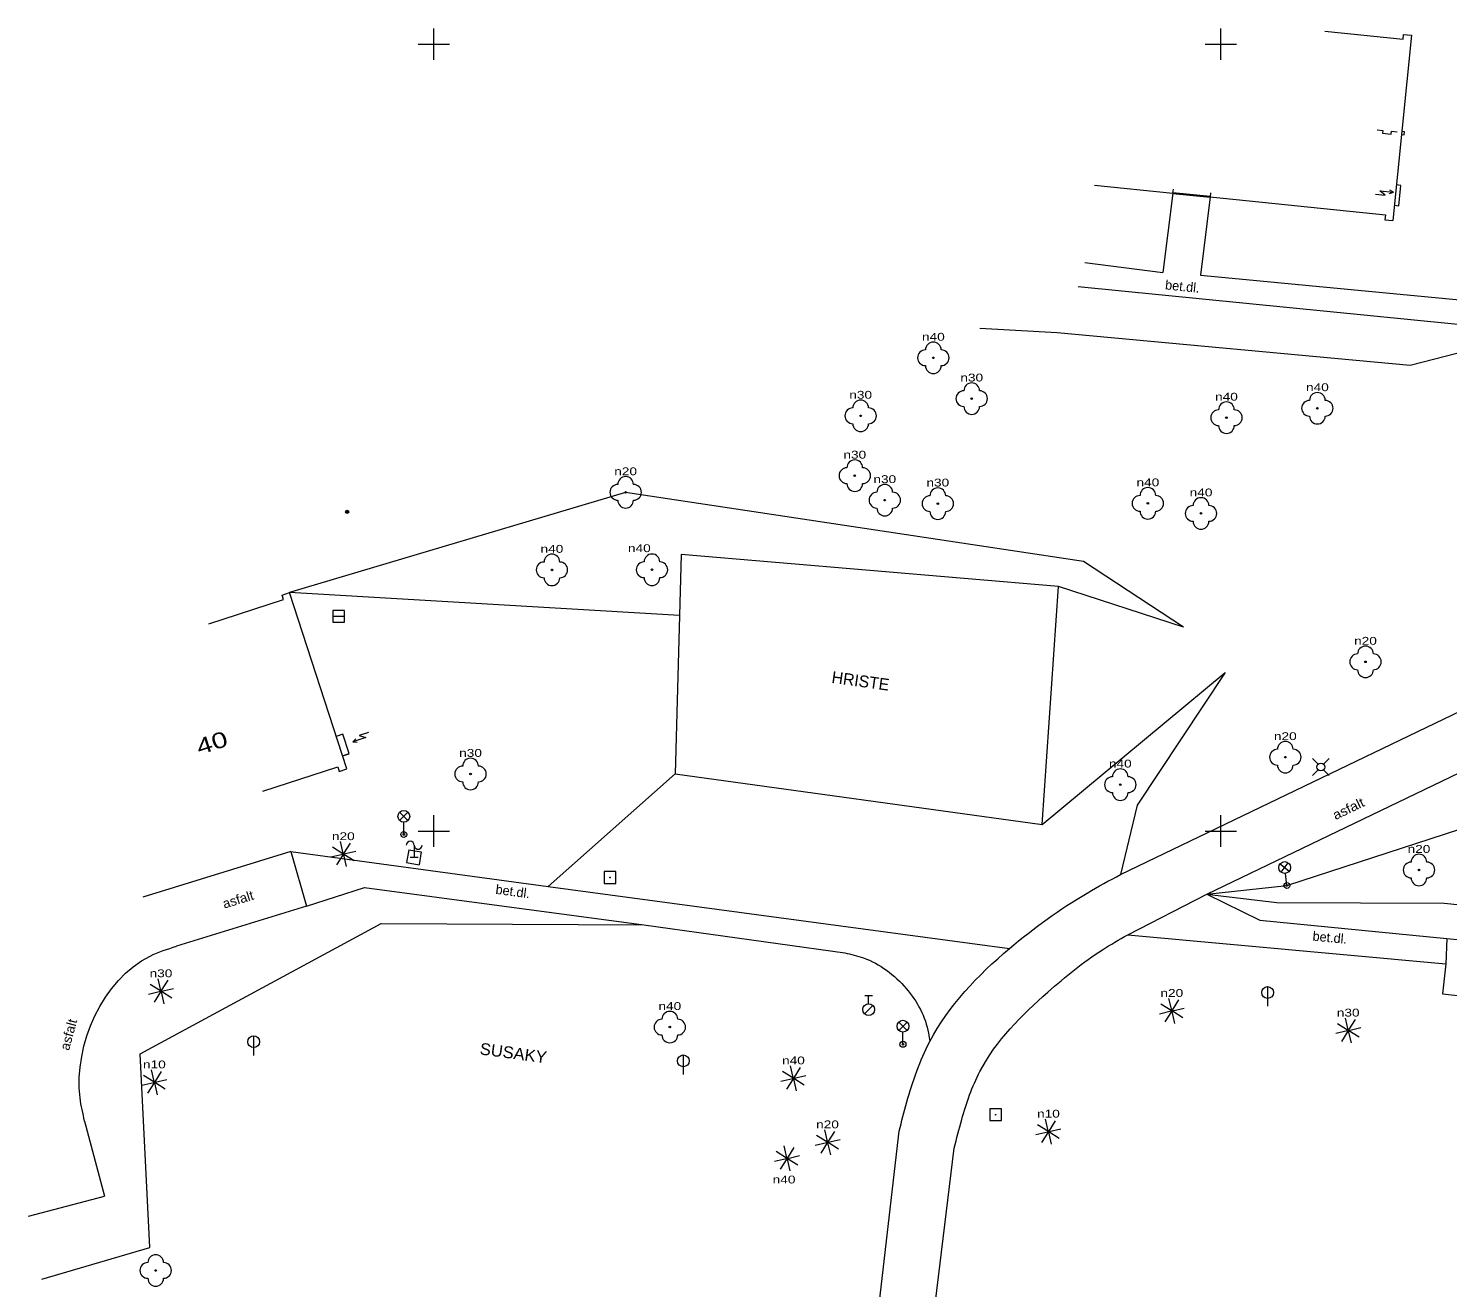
# Model space of a CAD drawing. Extents: x -670514 to -669423, y -1130798 to -1130123.
# Drawn here: x -670375.8 to -670285.6, y -1130379 to -1130299 of the extents above; entities that cross this region are included whole.
import ezdxf
from ezdxf.enums import TextEntityAlignment as Align

# ---------------------------------------------------------------- set-up
doc = ezdxf.new("R2010")
doc.units = 0
doc.header["$LTSCALE"] = 0.24
for name, color, linetype, lineweight in [('10', 7, 'Continuous', 13), ('11', 7, 'Continuous', 13), ('14', 7, 'Continuous', 13), ('22', 7, 'Continuous', 13), ('24', 7, 'Continuous', 13), ('25', 7, 'Continuous', 13), ('26', 7, 'Continuous', 13), ('27', 7, 'Continuous', 13), ('28', 7, 'Continuous', 13), ('31', 7, 'Continuous', 13), ('33', 7, 'Continuous', 13), ('36', 7, 'Continuous', 13), ('5', 7, 'Continuous', 13), ('6', 7, 'Continuous', 13), ('61', 7, 'Continuous', 13)]:
    doc.layers.add(name, color=color, linetype=linetype, lineweight=lineweight)
for name, color, linetype in [('40', 7, 'Continuous'), ('42', 7, 'Continuous'), ('44', 7, 'Continuous'), ('47', 7, 'Continuous')]:
    doc.layers.add(name, color=color, linetype=linetype)

msp = doc.modelspace()

# ---------------------------------------------------------------- linework, layer by layer
at = {"layer": '10'}
for p, q in [((-670303.039, -1130309.464), (-670303.685, -1130314.506)), ((-670308.644, -1130313.871), (-670303.685, -1130314.506)), ((-670306.368, -1130352.764), (-670262.03, -1130331.413)), ((-670359.087, -1130351.292), (-670368.502, -1130354.2)), ((-670358.089, -1130354.765), (-670366.357, -1130357.318)), ((-670305.915, -1130356.591), (-670285.692, -1130358.448)), ((-670285.636, -1130356.823), (-670266.032, -1130358.753)), ((-670285.692, -1130358.448), (-670285.913, -1130360.345)), ((-670372.192, -1130368.439), (-670370.934, -1130373.204)), ((-670323.828, -1130398.418), (-670320.435, -1130369.067)), ((-670375.768, -1130374.48), (-670370.934, -1130373.204))]:
    msp.add_line(p, q, dxfattribs=at)
for points in [[(-670300.676, -1130309.705), (-670301.286, -1130314.671), (-670268.591, -1130317.8)], [(-670262.03, -1130331.413), (-670267.808, -1130319.479), (-670279.819, -1130318.323), (-670309.071, -1130315.428)], [(-670305.915, -1130356.591), (-670300.884, -1130354.022), (-670260.5, -1130334.581)], [(-670359.087, -1130351.292), (-670342.735, -1130353.527), (-670313.434, -1130357.47)], [(-670358.089, -1130354.765), (-670354.419, -1130353.586), (-670336.653, -1130355.956), (-670323.879, -1130357.742)], [(-670300.884, -1130354.022), (-670297.511, -1130355.666), (-670285.636, -1130356.823)], [(-670285.913, -1130360.345), (-670284.549, -1130360.498), (-670266.966, -1130362.23)], [(-670327.052, -1130459.676), (-670322.78, -1130420.826), (-670319.03, -1130387.366), (-670316.938, -1130370.142)]]:
    msp.add_lwpolyline(points, dxfattribs=at)
for points in [[(-670320.435, -1130369.067), (-670319.945, -1130367.218), (-670318.491, -1130363.383), (-670313.434, -1130357.47), (-670308.484, -1130353.939), (-670306.368, -1130352.764)], [(-670316.938, -1130370.142), (-670316.46, -1130368.337), (-670315.299, -1130365.275), (-670310.985, -1130360.231), (-670307.518, -1130357.547), (-670305.915, -1130356.591)], [(-670372.192, -1130368.439), (-670372.481, -1130366.956), (-670368.032, -1130357.945), (-670366.357, -1130357.318)], [(-670323.879, -1130357.742), (-670322.707, -1130358.061), (-670319.988, -1130360.006), (-670318.568, -1130362.849), (-670318.491, -1130363.383)]]:
    msp.add_spline(points, degree=3, dxfattribs=at)
at = {"layer": '11'}
for p, q in [((-670359.087, -1130351.292), (-670358.089, -1130354.765)), ((-670285.636, -1130356.823), (-670285.692, -1130358.448))]:
    msp.add_line(p, q, dxfattribs=at)
msp.add_lwpolyline([(-670334.278, -1130332.433), (-670334.675, -1130346.357), (-670311.35, -1130349.586), (-670310.302, -1130334.46)], close=True, dxfattribs=at)
at = {"layer": '14'}
for p, q in [((-670302.357, -1130337.047), (-670310.302, -1130334.46)), ((-670334.389, -1130336.315), (-670359.169, -1130334.851)), ((-670311.35, -1130349.586), (-670299.73, -1130339.918)), ((-670334.675, -1130346.357), (-670342.735, -1130353.527))]:
    msp.add_line(p, q, dxfattribs=at)
for points in [[(-670279.819, -1130318.323), (-670287.973, -1130320.416), (-670310.397, -1130318.348), (-670315.318, -1130318.069)], [(-670302.357, -1130337.047), (-670308.712, -1130332.866), (-670337.818, -1130328.481), (-670359.169, -1130334.851)], [(-670299.73, -1130339.918), (-670305.304, -1130348.36), (-670306.368, -1130352.764)], [(-670300.884, -1130354.022), (-670295.798, -1130353.463), (-670282.08, -1130348.996)], [(-670300.884, -1130354.022), (-670296.445, -1130354.537), (-670285.8, -1130354.579)], [(-670285.8, -1130354.579), (-670266.083, -1130356.606), (-670253.016, -1130357.115), (-670247.888, -1130360.543)], [(-670374.922, -1130378.465), (-670368.058, -1130376.453), (-670368.663, -1130364.156), (-670353.348, -1130355.882), (-670336.653, -1130355.956)]]:
    msp.add_lwpolyline(points, dxfattribs=at)
at = {"layer": '22'}
for p, q in [((-670355.764, -1130351.425), (-670355.936, -1130350.671)), ((-670355.322, -1130350.775), (-670355.736, -1130351.431)), ((-670356.55, -1130351.645), (-670355.796, -1130351.473)), ((-670355.79, -1130351.445), (-670356.446, -1130351.031)), ((-670355.776, -1130351.499), (-670356.19, -1130352.155)), ((-670355.748, -1130351.505), (-670355.576, -1130352.259)), ((-670355.066, -1130351.899), (-670355.722, -1130351.485)), ((-670355.716, -1130351.457), (-670354.962, -1130351.285)), ((-670367.377, -1130360.157), (-670368.033, -1130359.743)), ((-670367.351, -1130360.137), (-670367.523, -1130359.383)), ((-670366.909, -1130359.487), (-670367.323, -1130360.143)), ((-670368.137, -1130360.357), (-670367.383, -1130360.185)), ((-670367.363, -1130360.211), (-670367.777, -1130360.867)), ((-670367.335, -1130360.217), (-670367.163, -1130360.971)), ((-670366.653, -1130360.611), (-670367.309, -1130360.197)), ((-670367.303, -1130360.169), (-670366.549, -1130359.997)), ((-670303.117, -1130361.387), (-670303.289, -1130360.633)), ((-670302.675, -1130360.737), (-670303.089, -1130361.393)), ((-670303.903, -1130361.607), (-670303.149, -1130361.435)), ((-670303.143, -1130361.407), (-670303.799, -1130360.993)), ((-670303.129, -1130361.461), (-670303.543, -1130362.117)), ((-670303.101, -1130361.467), (-670302.929, -1130362.221)), ((-670302.419, -1130361.861), (-670303.075, -1130361.447)), ((-670303.069, -1130361.419), (-670302.315, -1130361.247)), ((-670292.696, -1130362.855), (-670291.942, -1130362.683)), ((-670291.936, -1130362.655), (-670292.592, -1130362.241)), ((-670291.91, -1130362.635), (-670292.082, -1130361.881)), ((-670291.468, -1130361.985), (-670291.882, -1130362.641)), ((-670291.862, -1130362.667), (-670291.108, -1130362.495)), ((-670291.922, -1130362.709), (-670292.336, -1130363.365)), ((-670291.894, -1130362.715), (-670291.722, -1130363.469)), ((-670291.212, -1130363.109), (-670291.868, -1130362.695)), ((-670367.77, -1130365.925), (-670367.942, -1130365.171)), ((-670367.328, -1130365.275), (-670367.742, -1130365.931)), ((-670327.187, -1130365.692), (-670327.843, -1130365.278)), ((-670327.161, -1130365.672), (-670327.333, -1130364.918)), ((-670326.719, -1130365.022), (-670327.133, -1130365.678)), ((-670368.556, -1130366.145), (-670367.802, -1130365.973)), ((-670367.796, -1130365.945), (-670368.452, -1130365.531)), ((-670367.782, -1130365.999), (-670368.196, -1130366.655)), ((-670367.754, -1130366.005), (-670367.582, -1130366.759)), ((-670367.072, -1130366.399), (-670367.728, -1130365.985)), ((-670367.722, -1130365.957), (-670366.968, -1130365.785)), ((-670327.947, -1130365.892), (-670327.193, -1130365.72)), ((-670327.173, -1130365.746), (-670327.587, -1130366.402)), ((-670327.145, -1130365.752), (-670326.973, -1130366.506)), ((-670326.463, -1130366.146), (-670327.119, -1130365.732)), ((-670327.113, -1130365.704), (-670326.359, -1130365.532)), ((-670324.996, -1130369.735), (-670325.168, -1130368.981)), ((-670310.984, -1130369.076), (-670311.64, -1130368.662)), ((-670310.958, -1130369.056), (-670311.13, -1130368.302)), ((-670310.516, -1130368.406), (-670310.93, -1130369.062)), ((-670310.91, -1130369.088), (-670310.156, -1130368.916)), ((-670325.782, -1130369.955), (-670325.028, -1130369.783)), ((-670325.022, -1130369.755), (-670325.678, -1130369.341)), ((-670325.008, -1130369.809), (-670325.422, -1130370.465)), ((-670324.98, -1130369.815), (-670324.808, -1130370.569)), ((-670324.554, -1130369.085), (-670324.968, -1130369.741)), ((-670324.298, -1130370.209), (-670324.954, -1130369.795)), ((-670324.948, -1130369.767), (-670324.194, -1130369.595)), ((-670311.744, -1130369.276), (-670310.99, -1130369.104)), ((-670310.97, -1130369.13), (-670311.384, -1130369.786)), ((-670310.942, -1130369.136), (-670310.77, -1130369.89)), ((-670310.26, -1130369.53), (-670310.916, -1130369.116)), ((-670327.592, -1130370.786), (-670328.248, -1130370.372)), ((-670327.566, -1130370.766), (-670327.738, -1130370.012)), ((-670327.124, -1130370.116), (-670327.538, -1130370.772)), ((-670327.518, -1130370.798), (-670326.764, -1130370.626)), ((-670328.352, -1130370.986), (-670327.598, -1130370.814)), ((-670327.578, -1130370.84), (-670327.992, -1130371.496)), ((-670327.55, -1130370.846), (-670327.378, -1130371.6)), ((-670326.868, -1130371.24), (-670327.524, -1130370.826))]:
    msp.add_line(p, q, dxfattribs=at)
for centre, radius in [((-670318.263, -1130319.931), 0.05), ((-670315.824, -1130322.524), 0.05), ((-670322.883, -1130323.617), 0.05), ((-670299.638, -1130323.738), 0.05), ((-670293.859, -1130323.137), 0.05), ((-670323.256, -1130327.423), 0.05), ((-670337.818, -1130328.481), 0.05), ((-670321.35, -1130328.977), 0.05), ((-670317.98, -1130329.196), 0.05), ((-670304.631, -1130329.182), 0.05), ((-670301.254, -1130329.82), 0.05), ((-670342.5, -1130333.407), 0.05), ((-670336.145, -1130333.4), 0.05), ((-670290.803, -1130339.251), 0.05), ((-670295.9, -1130345.309), 0.05), ((-670347.671, -1130346.374), 0.05), ((-670306.385, -1130347.052), 0.05), ((-670355.756, -1130351.465), 0.04), ((-670287.406, -1130352.475), 0.05), ((-670367.343, -1130360.177), 0.04), ((-670303.109, -1130361.427), 0.04), ((-670335.009, -1130362.458), 0.05), ((-670291.902, -1130362.675), 0.04), ((-670367.762, -1130365.965), 0.04), ((-670327.153, -1130365.712), 0.04), ((-670324.988, -1130369.775), 0.04), ((-670310.95, -1130369.096), 0.04), ((-670327.558, -1130370.806), 0.04), ((-670367.677, -1130377.922), 0.05)]:
    msp.add_circle(centre, radius, dxfattribs=at)
for centre, start, end in [((-670318.263, -1130319.431), 0, 180), ((-670318.763, -1130319.931), 90, 270), ((-670317.763, -1130319.931), 270, 90), ((-670318.263, -1130320.431), 180, 0), ((-670316.324, -1130322.524), 90, 270), ((-670315.824, -1130322.024), 0, 180), ((-670315.324, -1130322.524), 270, 90), ((-670322.883, -1130323.117), 0, 180), ((-670299.638, -1130323.238), 0, 180), ((-670294.359, -1130323.137), 90, 270), ((-670293.859, -1130322.637), 0, 180), ((-670293.359, -1130323.137), 270, 90), ((-670323.383, -1130323.617), 90, 270), ((-670322.383, -1130323.617), 270, 90), ((-670315.824, -1130323.024), 180, 0), ((-670300.138, -1130323.738), 90, 270), ((-670299.138, -1130323.738), 270, 90), ((-670293.859, -1130323.637), 180, 0), ((-670322.883, -1130324.117), 180, 0), ((-670299.638, -1130324.238), 180, 0), ((-670323.256, -1130326.923), 0, 180), ((-670337.818, -1130327.981), 0, 180), ((-670323.756, -1130327.423), 90, 270), ((-670322.756, -1130327.423), 270, 90), ((-670338.318, -1130328.481), 90, 270), ((-670337.318, -1130328.481), 270, 90), ((-670323.256, -1130327.923), 180, 0), ((-670321.35, -1130328.477), 0, 180), ((-670317.98, -1130328.696), 0, 180), ((-670304.631, -1130328.682), 0, 180), ((-670337.818, -1130328.981), 180, 0), ((-670321.85, -1130328.977), 90, 270), ((-670320.85, -1130328.977), 270, 90), ((-670318.48, -1130329.196), 90, 270), ((-670317.48, -1130329.196), 270, 90), ((-670305.131, -1130329.182), 90, 270), ((-670304.131, -1130329.182), 270, 90), ((-670301.754, -1130329.82), 90, 270), ((-670301.254, -1130329.32), 0, 180), ((-670300.754, -1130329.82), 270, 90), ((-670321.35, -1130329.477), 180, 0), ((-670317.98, -1130329.696), 180, 0), ((-670304.631, -1130329.682), 180, 0), ((-670301.254, -1130330.32), 180, 0), ((-670343, -1130333.407), 90, 270), ((-670342.5, -1130332.907), 0, 180), ((-670342, -1130333.407), 270, 90), ((-670336.645, -1130333.4), 90, 270), ((-670336.145, -1130332.9), 0, 180), ((-670335.645, -1130333.4), 270, 90), ((-670342.5, -1130333.907), 180, 0), ((-670336.145, -1130333.9), 180, 0), ((-670290.803, -1130338.751), 0, 180), ((-670291.303, -1130339.251), 90, 270), ((-670290.303, -1130339.251), 270, 90), ((-670290.803, -1130339.751), 180, 0), ((-670295.9, -1130344.809), 0, 180), ((-670347.671, -1130345.874), 0, 180), ((-670296.4, -1130345.309), 90, 270), ((-670295.4, -1130345.309), 270, 90), ((-670348.171, -1130346.374), 90, 270), ((-670347.171, -1130346.374), 270, 90), ((-670306.385, -1130346.552), 0, 180), ((-670295.9, -1130345.809), 180, 0), ((-670347.671, -1130346.874), 180, 0), ((-670306.885, -1130347.052), 90, 270), ((-670305.885, -1130347.052), 270, 90), ((-670306.385, -1130347.552), 180, 0), ((-670287.406, -1130351.975), 0, 180), ((-670287.906, -1130352.475), 90, 270), ((-670286.906, -1130352.475), 270, 90), ((-670287.406, -1130352.975), 180, 0), ((-670335.009, -1130361.958), 0, 180), ((-670335.509, -1130362.458), 90, 270), ((-670334.509, -1130362.458), 270, 90), ((-670335.009, -1130362.958), 180, 0), ((-670367.677, -1130377.422), 0, 180), ((-670368.177, -1130377.922), 90, 270), ((-670367.177, -1130377.922), 270, 90), ((-670367.677, -1130378.422), 180, 0)]:
    msp.add_arc(centre, 0.5, start, end, dxfattribs=at)
at = {"layer": '24'}
for p, q in [((-670351.597, -1130351.192), (-670351.734, -1130352.01)), ((-670351.597, -1130351.192), (-670350.808, -1130351.324)), ((-670350.808, -1130351.324), (-670350.945, -1130352.142)), ((-670351.734, -1130352.01), (-670350.945, -1130352.142))]:
    msp.add_line(p, q, dxfattribs=at)
for points in [[(-670290.066, -1130305.447), (-670289.7, -1130305.485), (-670289.718, -1130305.667), (-670289.169, -1130305.722), (-670289.15, -1130305.54), (-670288.783, -1130305.575)], [(-670288.523, -1130305.752), (-670288.349, -1130305.769), (-670288.33, -1130305.577), (-670288.504, -1130305.56)], [(-670290.169, -1130309.541), (-670289.547, -1130309.604), (-670289.895, -1130309.317), (-670289.024, -1130309.405)], [(-670289.279, -1130309.49), (-670289.024, -1130309.405), (-670289.257, -1130309.271)], [(-670288.976, -1130310.24), (-670288.692, -1130310.269), (-670288.561, -1130308.975), (-670288.845, -1130308.946)], [(-670354.159, -1130343.741), (-670354.754, -1130343.934), (-670354.321, -1130344.056), (-670355.153, -1130344.326)], [(-670355.809, -1130345.222), (-670355.38, -1130345.083), (-670355.781, -1130343.846), (-670356.209, -1130343.985)], [(-670354.954, -1130344.146), (-670355.153, -1130344.326), (-670354.886, -1130344.355)]]:
    msp.add_lwpolyline(points, dxfattribs=at)
at = {"layer": '25'}
for radius in [0.1002, 0.0348]:
    msp.add_circle((-670355.512, -1130329.721), radius, dxfattribs=at)
at = {"layer": '26'}
for points in [[(-670339.179, -1130353.325), (-670338.429, -1130353.325), (-670338.429, -1130352.575), (-670339.179, -1130352.575)], [(-670314.683, -1130368.403), (-670313.933, -1130368.403), (-670313.933, -1130367.653), (-670314.683, -1130367.653)]]:
    msp.add_lwpolyline(points, close=True, dxfattribs=at)
for centre in [(-670338.8039, -1130352.95), (-670314.3079, -1130368.028)]:
    msp.add_circle(centre, 0.02, dxfattribs=at)
at = {"layer": '27'}
for p, q in [((-670356.423, -1130336.356), (-670355.673, -1130336.356)), ((-670297.024, -1130359.888), (-670297.024, -1130361.138)), ((-670361.455, -1130363.015), (-670361.455, -1130364.265)), ((-670334.151, -1130364.23), (-670334.151, -1130365.48))]:
    msp.add_line(p, q, dxfattribs=at)
msp.add_lwpolyline([(-670356.423, -1130336.73), (-670355.673, -1130336.73), (-670355.673, -1130335.98), (-670356.423, -1130335.98)], close=True, dxfattribs=at)
for centre in [(-670297.0236, -1130360.2631), (-670361.4546, -1130363.3901), (-670334.1506, -1130364.6051)]:
    msp.add_circle(centre, 0.375, dxfattribs=at)
at = {"layer": '28'}
for p, q in [((-670322.624, -1130360.449), (-670322.124, -1130360.449)), ((-670322.374, -1130360.974), (-670322.374, -1130360.449)), ((-670322.639, -1130361.614), (-670322.109, -1130361.084))]:
    msp.add_line(p, q, dxfattribs=at)
msp.add_circle((-670322.374, -1130361.349), 0.375, dxfattribs=at)
at = {"layer": '31'}
for p, q in [((-670294.174, -1130345.401), (-670293.819, -1130345.756)), ((-670293.465, -1130345.755), (-670293.111, -1130345.402)), ((-670293.819, -1130346.109), (-670294.172, -1130346.463)), ((-670293.466, -1130346.108), (-670293.111, -1130346.463))]:
    msp.add_line(p, q, dxfattribs=at)
msp.add_circle((-670293.6418, -1130345.9326), 0.25, dxfattribs=at)
at = {"layer": '33'}
for p, q in [((-670352.176, -1130348.803), (-670351.646, -1130349.333)), ((-670352.176, -1130349.333), (-670351.646, -1130348.803)), ((-670351.911, -1130350.218), (-670351.911, -1130349.443)), ((-670296.234, -1130352.091), (-670295.643, -1130352.552)), ((-670296.169, -1130352.617), (-670295.708, -1130352.026)), ((-670295.798, -1130353.463), (-670295.893, -1130352.694)), ((-670320.461, -1130362.136), (-670319.931, -1130362.666)), ((-670320.461, -1130362.666), (-670319.931, -1130362.136)), ((-670320.196, -1130363.551), (-670320.196, -1130362.776))]:
    msp.add_line(p, q, dxfattribs=at)
for centre, radius in [((-670351.911, -1130349.068), 0.375), ((-670351.911, -1130350.218), 0.19), ((-670351.911, -1130350.218), 0.05), ((-670295.9386, -1130352.3216), 0.375), ((-670295.798, -1130353.463), 0.19), ((-670295.798, -1130353.463), 0.05), ((-670320.196, -1130362.401), 0.375), ((-670320.196, -1130363.551), 0.19), ((-670320.196, -1130363.551), 0.05)]:
    msp.add_circle(centre, radius, dxfattribs=at)
at = {"layer": '36'}
for p, q in [((-670351.252, -1130350.903), (-670351.254, -1130351.657)), ((-670351.502, -1130351.653), (-670351.002, -1130351.653))]:
    msp.add_line(p, q, dxfattribs=at)
for centre, start, end in [((-670351.502, -1130350.903), 0, 180), ((-670351.002, -1130350.903), 178.62516, 0)]:
    msp.add_arc(centre, 0.25, start, end, dxfattribs=at)
at = {"layer": '5'}
for p, q in [((-670293.389, -1130299.183), (-670288.414, -1130299.684)), ((-670287.887, -1130299.436), (-670289.073, -1130311.205)), ((-670288.414, -1130299.684), (-670288.384, -1130299.386)), ((-670288.384, -1130299.386), (-670287.887, -1130299.436)), ((-670308.013, -1130308.957), (-670303.039, -1130309.464)), ((-670300.676, -1130309.705), (-670289.54, -1130310.857)), ((-670289.54, -1130310.857), (-670289.57, -1130311.155)), ((-670289.57, -1130311.155), (-670289.073, -1130311.205)), ((-670364.311, -1130336.826), (-670359.553, -1130335.29)), ((-670359.645, -1130335.005), (-670359.169, -1130334.851)), ((-670359.553, -1130335.29), (-670359.645, -1130335.005)), ((-670355.538, -1130346.057), (-670359.169, -1130334.851)), ((-670355.809, -1130345.222), (-670355.393, -1130345.087)), ((-670360.864, -1130347.462), (-670356.106, -1130345.926)), ((-670356.106, -1130345.926), (-670356.014, -1130346.211)), ((-670356.014, -1130346.211), (-670355.538, -1130346.057))]:
    msp.add_line(p, q, dxfattribs=at)
at = {"layer": '6'}
for p, q in [((-670303.039, -1130309.464), (-670303.013, -1130309.215)), ((-670300.65, -1130309.456), (-670300.676, -1130309.705))]:
    msp.add_line(p, q, dxfattribs=at)
at = {"layer": '6', "lineweight": 35}
msp.add_line((-670303.039, -1130309.464), (-670300.676, -1130309.705), dxfattribs=at)
at = {"layer": '61'}
for p, q in [((-670350, -1130301), (-670350, -1130299)), ((-670300, -1130301), (-670300, -1130299)), ((-670351, -1130300), (-670349, -1130300)), ((-670301, -1130300), (-670299, -1130300)), ((-670350, -1130351), (-670350, -1130349)), ((-670300, -1130351), (-670300, -1130349)), ((-670351, -1130350), (-670349, -1130350)), ((-670301, -1130350), (-670299, -1130350))]:
    msp.add_line(p, q, dxfattribs=at)

# ---------------------------------------------------------------- texts
at = {"layer": '22', "width": 1.3}
for s, p in [('n40', (-670318.2625, -1130318.845)), ('n30', (-670315.8235, -1130321.438)), ('n30', (-670322.8825, -1130322.531)), ('n40', (-670293.8585, -1130322.051)), ('n40', (-670299.6375, -1130322.652)), ('n30', (-670323.2555, -1130326.337)), ('n20', (-670337.8175, -1130327.395)), ('n30', (-670321.3495, -1130327.891)), ('n30', (-670317.9795, -1130328.11)), ('n40', (-670304.6305, -1130328.096)), ('n40', (-670301.2535, -1130328.734)), ('n40', (-670342.4995, -1130332.321)), ('n40', (-670336.9465, -1130332.279)), ('n20', (-670290.8025, -1130338.165)), ('n20', (-670295.8995, -1130344.223)), ('n30', (-670347.6705, -1130345.288)), ('n40', (-670306.3845, -1130345.966)), ('n20', (-670355.7565, -1130350.579)), ('n20', (-670287.4055, -1130351.389)), ('n30', (-670367.3435, -1130359.291)), ('n40', (-670335.0085, -1130361.372)), ('n20', (-670303.1095, -1130360.541)), ('n30', (-670291.9025, -1130361.789)), ('n40', (-670327.1535, -1130364.826)), ('n10', (-670367.7625, -1130365.079)), ('n10', (-670310.9505, -1130368.21)), ('n20', (-670324.9885, -1130368.889))]:
    msp.add_text(s, height=0.499, dxfattribs=at).set_placement(p, align=Align.CENTER)
at = {"layer": '40'}
for rotation, p in [(354.348, (-670302.467, -1130315.6886)), (352.402, (-670345.0252, -1130354.1337)), (354.753, (-670293.0954, -1130357.0651))]:
    msp.add_text('bet.dl.', height=0.6, rotation=rotation, dxfattribs=at).set_placement(p, align=Align.CENTER)
for rotation, width, p in [(25.706, 1.1, (-670291.7576, -1130348.8509)), (17.16, 1.05, (-670362.3565, -1130354.6353)), (74.684, 1.05, (-670372.925, -1130363.0117))]:
    msp.add_text('asfalt', height=0.6, rotation=rotation, dxfattribs=dict(at, width=width)).set_placement(p, align=Align.CENTER)
at = {"layer": '42'}
msp.add_text('HRISTE', height=0.75, rotation=352.118, dxfattribs=at).set_placement((-670322.9389, -1130340.8347), align=Align.CENTER)
at = {"layer": '42', "width": 1.05}
msp.add_text('SUSAKY', height=0.75, rotation=352.336, dxfattribs=at).set_placement((-670345.002, -1130364.4753), align=Align.CENTER)
at = {"layer": '44', "width": 1.35}
msp.add_text('40', height=1, rotation=17.891, dxfattribs=at).set_placement((-670363.9521, -1130344.8692), align=Align.CENTER)
at = {"layer": '47', "width": 1.3}
msp.add_text('n40', height=0.5, dxfattribs=at).set_placement((-670327.7495, -1130372.395), align=Align.CENTER)

doc.saveas('drawing.dxf')
